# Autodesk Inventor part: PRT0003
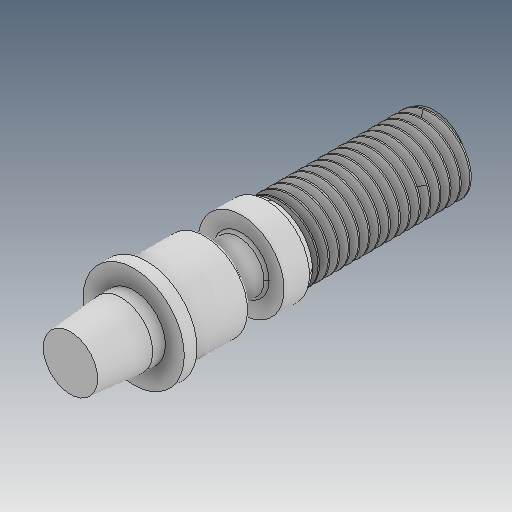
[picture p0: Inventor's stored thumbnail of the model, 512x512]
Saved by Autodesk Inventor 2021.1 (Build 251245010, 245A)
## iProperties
Created: 2019-04
Part Number: PRT0003
Material: Ogólny
Document SubType Name: Modeling
Designer: user
Density: 1 g/cm^3
Appearance: Domyślna
Author: user
Revision Number: ÈÎºÎ
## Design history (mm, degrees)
feature "ÊäÈë1"
node "Bryła1"
